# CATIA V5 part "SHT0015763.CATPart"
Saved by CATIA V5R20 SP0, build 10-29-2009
Part number: Part2
Bounding box of the stored display mesh (mm): x 0 to 60, y 0 to 45.615, z -9.028 to 78.282
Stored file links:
  E:\项目\EST新造型泡沫\坐垫增加硬质棉数据\硬质棉\SHT0015763.CATPart

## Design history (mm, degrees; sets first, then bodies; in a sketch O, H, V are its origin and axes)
Body1 (main body)
  Sketch1 on yz-plane, origin (0, 0, 0), H (0, 1, 0), V (0, 0, 1)
    line L1 (0, 0) -> (0, 70)
    arc A1 centre (8.3, 70) radius 8.3 from (0, 70) to (16.108, 72.815) cw
    line L2 (16.108, 72.815) -> (45.6151, -9.0283)
    line L3 (45.6151, -9.0283) -> (0, 0)
    length L1 = 70
    length L2 = 87
    length L3 = 46.5
    radius A1 = 8.3
    vertical: L1 V
    tangency: A1 L1, L2 A1
  Pad1: profile Sketch1, direction (1, 0, 0), length 60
